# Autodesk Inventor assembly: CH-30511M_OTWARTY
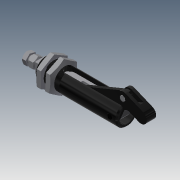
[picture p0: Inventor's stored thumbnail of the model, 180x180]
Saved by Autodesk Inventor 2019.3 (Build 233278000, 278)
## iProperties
Company: ·L?¤¤?
Created: 2010-06
Part Number: CH-30511M_OTWARTY
Material: Ogólny
Description: STEP AP203
Document SubType Name: Assembly
Designer: CADENGINEERING4
Sending System: SolidWorks 2005179
Preprocessor: SwSTEP 2.0
Title: CH-30511M.STEP
Author: ·L?¥Î?
Revision Number: ANY
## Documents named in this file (12)
- D:\Vault_2016\Projekty\STRONA\Push-pull clamp\CH-30511M\CH-30511M_OTWARTY.iam
- D:\Vault_2016\Projekty\STRONA\Push-pull clamp\CH-30511M\CH-30511M-01___.ipt
- D:\Vault_2016\Projekty\STRONA\Push-pull clamp\CH-30511M\CH-30510M-04___.ipt
- D:\Vault_2016\Projekty\STRONA\Push-pull clamp\CH-30511M\CH-30511M-02___.ipt
- D:\Vault_2016\Projekty\STRONA\Push-pull clamp\CH-30511M\M12___.ipt
- D:\Vault_2016\Projekty\STRONA\Push-pull clamp\CH-30511M\CH-30509-08___.ipt
- D:\Vault_2016\Projekty\STRONA\Push-pull clamp\CH-30511M\CH-30510M-03___.ipt
- D:\Vault_2016\Projekty\STRONA\Push-pull clamp\CH-30511M\CH-30509-07___.ipt
- D:\Vault_2016\Projekty\STRONA\Push-pull clamp\CH-30511M\M12X50___.ipt
- D:\Vault_2016\Projekty\STRONA\Push-pull clamp\CH-30511M\CH-30510M-02___.ipt
- D:\Vault_2016\Projekty\STRONA\Push-pull clamp\CH-30511M\CH-30509-06___.ipt
- D:\Vault_2016\Projekty\STRONA\Push-pull clamp\CH-30511M\CH-30509-09___.ipt
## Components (12 placed, 12 different names)
1. CH-30511M-01_??_1 — Równoległe:1, Zestawiające:2, Zestawiające:3, Zestawiające:8, Zestawiające:9, Zestawiające:17, Zestawiające:18
2. CH-30510M-04_??_2 — Zestawiające:12, Zestawiające:13, Zestawiające:14, Zestawiające:15, Kątowe:1
3. CH-30511M-02_??_3 — Zestawiające:1, Równoległe:1, Zestawiające:3
4. M12_??_4 — Zestawiające:4, Zestawiające:5, Zestawiające:6
5. CH-30509-08_??_5 — Zestawiające:14, Równoległe:4
6. CH-30510M-03_??_6 — Zestawiające:8, Zestawiające:9, Zestawiające:10, Równoległe:2, Równoległe:3, Zestawiające:12, Zestawiające:13, Równoległe:4, Kątowe:1
7. CH-30509-07_??_7 — Zestawiające:16
8. M12X50_??_8 — Zestawiające:4, Zestawiające:6, Zestawiające:7
9. CH-30510M-02_??_9 — Zestawiające:5, Zestawiające:7, Zestawiające:15, Zestawiające:16, Zestawiające:17, Zestawiające:18
10. CH-30511M-02_??_10 — Zestawiające:1, Zestawiające:2
11. CH-30509-06_??_11 — Zestawiające:11, Równoległe:3
12. CH-30509-09_??_12 — Zestawiające:10, Równoległe:2, Zestawiające:11
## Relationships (23: Mate 18, Flush 4, Angle 1)
- Zestawiające:1 [Mate]: CH-30511M-02_??_3 ↔ CH-30511M-02_??_10
- Równoległe:1 [Flush]: CH-30511M-01_??_1 ↔ CH-30511M-02_??_3
- Zestawiające:2 [Mate]: CH-30511M-01_??_1 ↔ CH-30511M-02_??_10
- Zestawiające:3 [Mate]: CH-30511M-01_??_1 ↔ CH-30511M-02_??_3
- Zestawiające:4 [Mate]: M12_??_4 ↔ M12X50_??_8
- Zestawiające:5 [Mate]: M12_??_4 ↔ CH-30510M-02_??_9
- Zestawiające:6 [Mate]: M12_??_4 ↔ M12X50_??_8
- Zestawiające:7 [Mate]: M12X50_??_8 ↔ CH-30510M-02_??_9
- Zestawiające:8 [Mate]: CH-30511M-01_??_1 ↔ CH-30510M-03_??_6
- Zestawiające:9 [Mate]: CH-30511M-01_??_1 ↔ CH-30510M-03_??_6
- Zestawiające:10 [Mate]: CH-30510M-03_??_6 ↔ CH-30509-09_??_12
- Równoległe:2 [Flush]: CH-30510M-03_??_6 ↔ CH-30509-09_??_12
- Zestawiające:11 [Mate]: CH-30509-06_??_11 ↔ CH-30509-09_??_12
- Równoległe:3 [Flush]: CH-30510M-03_??_6 ↔ CH-30509-06_??_11
- Zestawiające:12 [Mate]: CH-30510M-04_??_2 ↔ CH-30510M-03_??_6
- Zestawiające:13 [Mate]: CH-30510M-04_??_2 ↔ CH-30510M-03_??_6
- Zestawiające:14 [Mate]: CH-30510M-04_??_2 ↔ CH-30509-08_??_5
- Równoległe:4 [Flush]: CH-30509-08_??_5 ↔ CH-30510M-03_??_6
- Zestawiające:15 [Mate]: CH-30510M-04_??_2 ↔ CH-30510M-02_??_9
- Zestawiające:16 [Mate]: CH-30509-07_??_7 ↔ CH-30510M-02_??_9
- Zestawiające:17 [Mate]: CH-30511M-01_??_1 ↔ CH-30510M-02_??_9
- Zestawiające:18 [Mate]: CH-30511M-01_??_1 ↔ CH-30510M-02_??_9
- Kątowe:1 [Angle]: CH-30510M-04_??_2 ↔ CH-30510M-03_??_6
